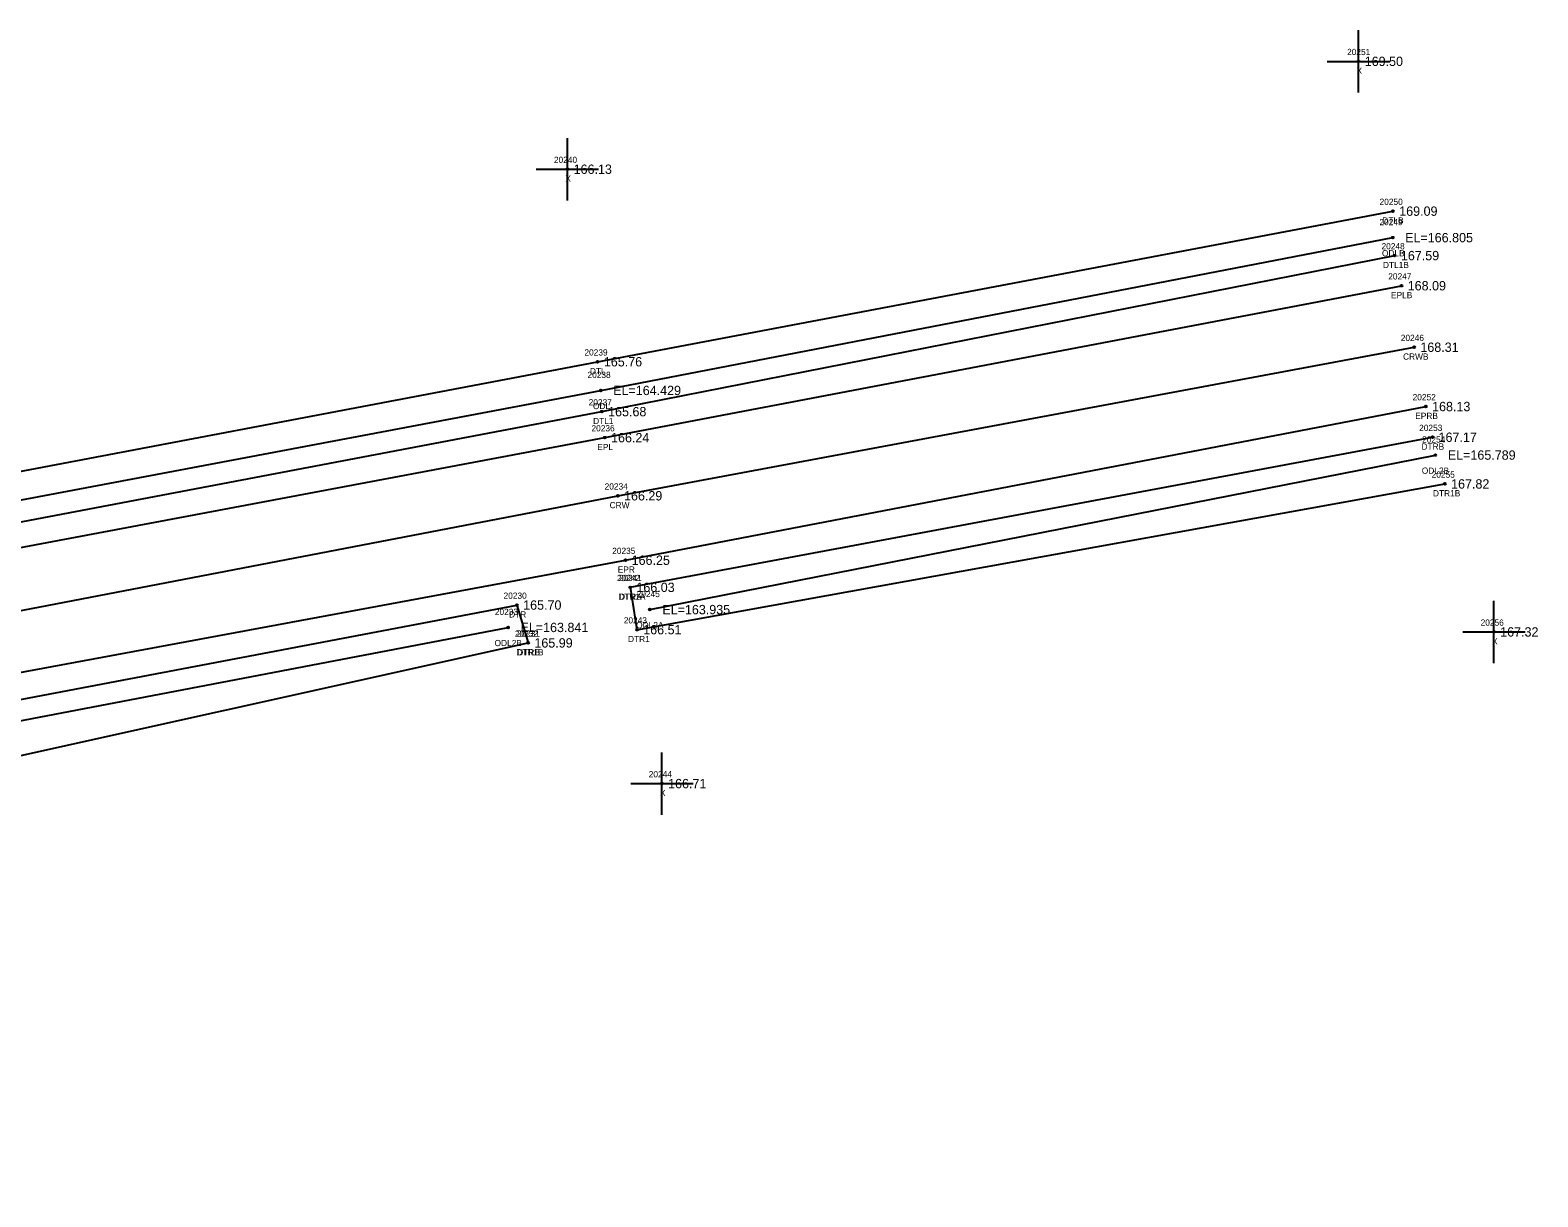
# Model space of a CAD drawing. Extents: x 2381545 to 2382928, y 1029933 to 1030589.
# Drawn here: x 2382686.7 to 2382928.4, y 1030367.7 to 1030554.8 of the extents above; entities that cross this region are included whole.
import ezdxf

# ---------------------------------------------------------------- set-up
doc = ezdxf.new("R2010")
doc.units = 0
for name, color, linetype in [('RD_DTM_BkLn1', 7, 'Continuous'), ('RD_EX_H2O', 7, 'Continuous'), ('RD_EX_H2O_txCode', 7, 'Continuous'), ('RD_EX_Misc', 7, 'Continuous'), ('RD_EX_Misc_txCode', 7, 'Continuous'), ('RD_EX_Road', 7, 'Continuous'), ('RD_EX_Road_txCode', 7, 'Continuous'), ('RD_EX_TX_H2O_ELEV', 7, 'Continuous'), ('RD_EX_TX_Misc_ELEV', 7, 'Continuous'), ('RD_EX_TX_Road_ELEV', 7, 'Continuous'), ('RD_HC_Survey_ELEV', 7, 'Continuous'), ('RD_HC_Survey_txCode', 7, 'Continuous'), ('RD_SMD_Locator', 7, 'Continuous')]:
    doc.layers.add(name, color=color, linetype=linetype)

msp = doc.modelspace()

# ---------------------------------------------------------------- linework, layer by layer
at = {"layer": 'RD_DTM_BkLn1'}
msp.add_lwpolyline([(2382237.83, 1030377.97), (2382343.9, 1030397.77), (2382436.97, 1030414.87), (2382557.72, 1030437.27), (2382666.29, 1030458.08), (2382780.92, 1030480.13), (2382908.6, 1030503.95)], dxfattribs=at)
at = {"layer": 'RD_EX_H2O'}
for p, q in [((2382782.9, 1030465.45), (2382911.52, 1030489.52)), ((2382786.06, 1030461.88), (2382912, 1030486.66))]:
    msp.add_line(p, q, dxfattribs=at)
for points in [[(2382466.62, 1030439.12), (2382470.56, 1030441.45), (2382553.99, 1030457.35), (2382661.6, 1030479.57), (2382777.69, 1030501.62), (2382905.21, 1030525.77)], [(2382466.62, 1030439.12), (2382471.06, 1030439.47), (2382554.93, 1030454.98), (2382662.31, 1030475.15), (2382778.18, 1030497.02), (2382905.16, 1030521.52)], [(2382466.62, 1030439.12), (2382471.74, 1030437.5), (2382555.22, 1030451.65), (2382662.97, 1030471.73), (2382778.37, 1030493.62), (2382905.48, 1030518.64)], [(2382782.9, 1030465.45), (2382784, 1030458.66), (2382913.53, 1030482.03)], [(2382424.24, 1030390.04), (2382440.08, 1030397.96), (2382560.33, 1030423.53), (2382668.22, 1030444.25), (2382764.75, 1030462.61), (2382766.55, 1030456.54)], [(2382424.24, 1030390.04), (2382440.69, 1030395.22), (2382560.27, 1030420.72), (2382668.78, 1030440.95), (2382763.32, 1030459.02)], [(2382424.24, 1030390.04), (2382441.2, 1030392.41), (2382561.56, 1030416.11), (2382669.3, 1030434.96), (2382766.55, 1030456.54)]]:
    msp.add_lwpolyline(points, dxfattribs=at)
at = {"layer": 'RD_EX_Misc'}
for p, q in [((2382899.68, 1030544.79), (2382899.68, 1030554.79)), ((2382894.68, 1030549.79), (2382904.68, 1030549.79)), ((2382772.84, 1030527.49), (2382772.84, 1030537.49)), ((2382767.84, 1030532.49), (2382777.84, 1030532.49)), ((2382921.4, 1030453.3), (2382921.4, 1030463.3)), ((2382916.4, 1030458.3), (2382926.4, 1030458.3)), ((2382787.99, 1030428.98), (2382787.99, 1030438.98)), ((2382782.99, 1030433.98), (2382792.99, 1030433.98))]:
    msp.add_line(p, q, dxfattribs=at)
at = {"layer": 'RD_EX_Road'}
for points in [[(2382237.83, 1030377.97), (2382235.13, 1030386.42), (2382342.38, 1030406.92), (2382435.08, 1030424.16), (2382555.51, 1030447.01), (2382663.83, 1030467.83), (2382778.84, 1030489.45), (2382906.57, 1030513.81)], [(2382237.83, 1030377.97), (2382241.1, 1030367.72), (2382346.41, 1030388.08), (2382437.98, 1030404.17), (2382559.51, 1030427.48), (2382667.4, 1030448.54), (2382782.14, 1030469.8), (2382910.48, 1030494.44)]]:
    msp.add_lwpolyline(points, dxfattribs=at)
at = {"layer": 'RD_SMD_Locator'}
for centre in [(2382899.68, 1030549.79), (2382772.84, 1030532.49), (2382905.21, 1030525.77), (2382905.16, 1030521.52), (2382905.48, 1030518.64), (2382906.57, 1030513.81), (2382908.6, 1030503.95), (2382777.69, 1030501.62), (2382778.18, 1030497.02), (2382778.37, 1030493.62), (2382910.48, 1030494.44), (2382778.84, 1030489.45), (2382911.52, 1030489.52), (2382912, 1030486.66), (2382913.53, 1030482.03), (2382780.92, 1030480.13), (2382782.14, 1030469.8), (2382782.9, 1030465.45), (2382782.9, 1030465.45), (2382764.75, 1030462.61), (2382786.06, 1030461.88), (2382763.32, 1030459.02), (2382784, 1030458.66), (2382766.55, 1030456.54), (2382766.55, 1030456.54), (2382921.4, 1030458.3), (2382787.99, 1030433.98)]:
    msp.add_circle(centre, 0.15, dxfattribs=at)

# ---------------------------------------------------------------- texts
at = {"layer": 'RD_EX_H2O_txCode'}
for s, p in [('20250', (2382903.06, 1030526.77)), ('20249', (2382903.04, 1030523.52)), ('DTLB', (2382903.5, 1030523.77)), ('20248', (2382903.37, 1030519.64)), ('ODLB', (2382903.44, 1030518.52)), ('DTL1B', (2382903.6, 1030516.64)), ('20239', (2382775.57, 1030502.62)), ('20238', (2382776.06, 1030499.02)), ('DTL', (2382776.45, 1030499.62)), ('20237', (2382776.25, 1030494.62)), ('ODL', (2382776.94, 1030494.02)), ('DTL1', (2382776.96, 1030491.62)), ('20253', (2382909.4, 1030490.52)), ('DTRB', (2382909.78, 1030487.52)), ('20254', (2382909.88, 1030488.66)), ('ODL2B', (2382909.83, 1030483.66)), ('20255', (2382911.41, 1030483.03)), ('DTR1B', (2382911.62, 1030480.03)), ('20242', (2382780.78, 1030466.45)), ('20241', (2382781.06, 1030466.45)), ('20230', (2382762.6, 1030463.61)), ('DTR1A', (2382780.98, 1030463.45)), ('DTRA', (2382781.14, 1030463.45)), ('20245', (2382783.94, 1030463.88)), ('20233', (2382761.21, 1030461.02)), ('DTR', (2382763.49, 1030460.61)), ('20243', (2382781.88, 1030459.66)), ('ODL2A', (2382783.87, 1030458.88)), ('ODL2B', (2382761.16, 1030456.02)), ('20232', (2382764.43, 1030457.54)), ('20231', (2382764.72, 1030457.54)), ('DTR1', (2382782.56, 1030456.66)), ('DTR1B', (2382764.64, 1030454.54)), ('DTRB', (2382764.81, 1030454.54))]:
    msp.add_text(s, height=1, dxfattribs=at).set_placement(p)
at = {"layer": 'RD_EX_Misc_txCode'}
for s, p in [('20251', (2382897.85, 1030550.79)), ('X', (2382899.37, 1030547.79)), ('20240', (2382770.68, 1030533.49)), ('X', (2382772.52, 1030530.49)), ('20256', (2382919.26, 1030459.3)), ('X', (2382921.09, 1030456.3)), ('20244', (2382785.88, 1030434.98)), ('X', (2382787.68, 1030431.98))]:
    msp.add_text(s, height=1, dxfattribs=at).set_placement(p)
at = {"layer": 'RD_EX_Road_txCode'}
for s, p in [('20247', (2382904.45, 1030514.81)), ('EPLB', (2382904.89, 1030511.81)), ('20252', (2382908.36, 1030495.44)), ('EPRB', (2382908.78, 1030492.44)), ('20236', (2382776.7, 1030490.45)), ('EPL', (2382777.63, 1030487.45)), ('20235', (2382780.02, 1030470.8)), ('EPR', (2382780.91, 1030467.8))]:
    msp.add_text(s, height=1, dxfattribs=at).set_placement(p)
at = {"layer": 'RD_EX_TX_H2O_ELEV'}
for s, p in [('169.09', (2382906.21, 1030525.02)), ('EL=166.805', (2382907.16, 1030520.77)), ('167.59', (2382906.48, 1030517.89)), ('165.76', (2382778.69, 1030500.87)), ('EL=164.429', (2382780.18, 1030496.27)), ('165.68', (2382779.37, 1030492.87)), ('167.17', (2382912.52, 1030488.77)), ('EL=165.789', (2382914, 1030485.91)), ('167.82', (2382914.53, 1030481.28)), ('166.03', (2382783.9, 1030464.7)), ('166.03', (2382783.9, 1030464.7)), ('165.70', (2382765.75, 1030461.86)), ('EL=163.935', (2382788.06, 1030461.13)), ('EL=163.841', (2382765.32, 1030458.27)), ('166.51', (2382785, 1030457.91)), ('165.99', (2382767.55, 1030455.79)), ('165.99', (2382767.55, 1030455.79))]:
    msp.add_text(s, height=1.5, dxfattribs=at).set_placement(p)
at = {"layer": 'RD_EX_TX_Misc_ELEV'}
for s, p in [('169.50', (2382900.68, 1030549.04)), ('166.13', (2382773.84, 1030531.74)), ('167.32', (2382922.4, 1030457.55)), ('166.71', (2382788.99, 1030433.23))]:
    msp.add_text(s, height=1.5, dxfattribs=at).set_placement(p)
at = {"layer": 'RD_EX_TX_Road_ELEV'}
for s, p in [('168.09', (2382907.57, 1030513.06)), ('168.13', (2382911.48, 1030493.69)), ('166.24', (2382779.84, 1030488.7)), ('166.25', (2382783.14, 1030469.05))]:
    msp.add_text(s, height=1.5, dxfattribs=at).set_placement(p)
at = {"layer": 'RD_HC_Survey_ELEV'}
for s, p in [('168.31', (2382909.6, 1030503.2)), ('166.29', (2382781.92, 1030479.38))]:
    msp.add_text(s, height=1.5, dxfattribs=at).set_placement(p)
at = {"layer": 'RD_HC_Survey_txCode'}
for s, p in [('20246', (2382906.46, 1030504.95)), ('CRWB', (2382906.82, 1030501.95)), ('20234', (2382778.81, 1030481.13)), ('CRW', (2382779.61, 1030478.13))]:
    msp.add_text(s, height=1, dxfattribs=at).set_placement(p)

doc.saveas('drawing.dxf')
